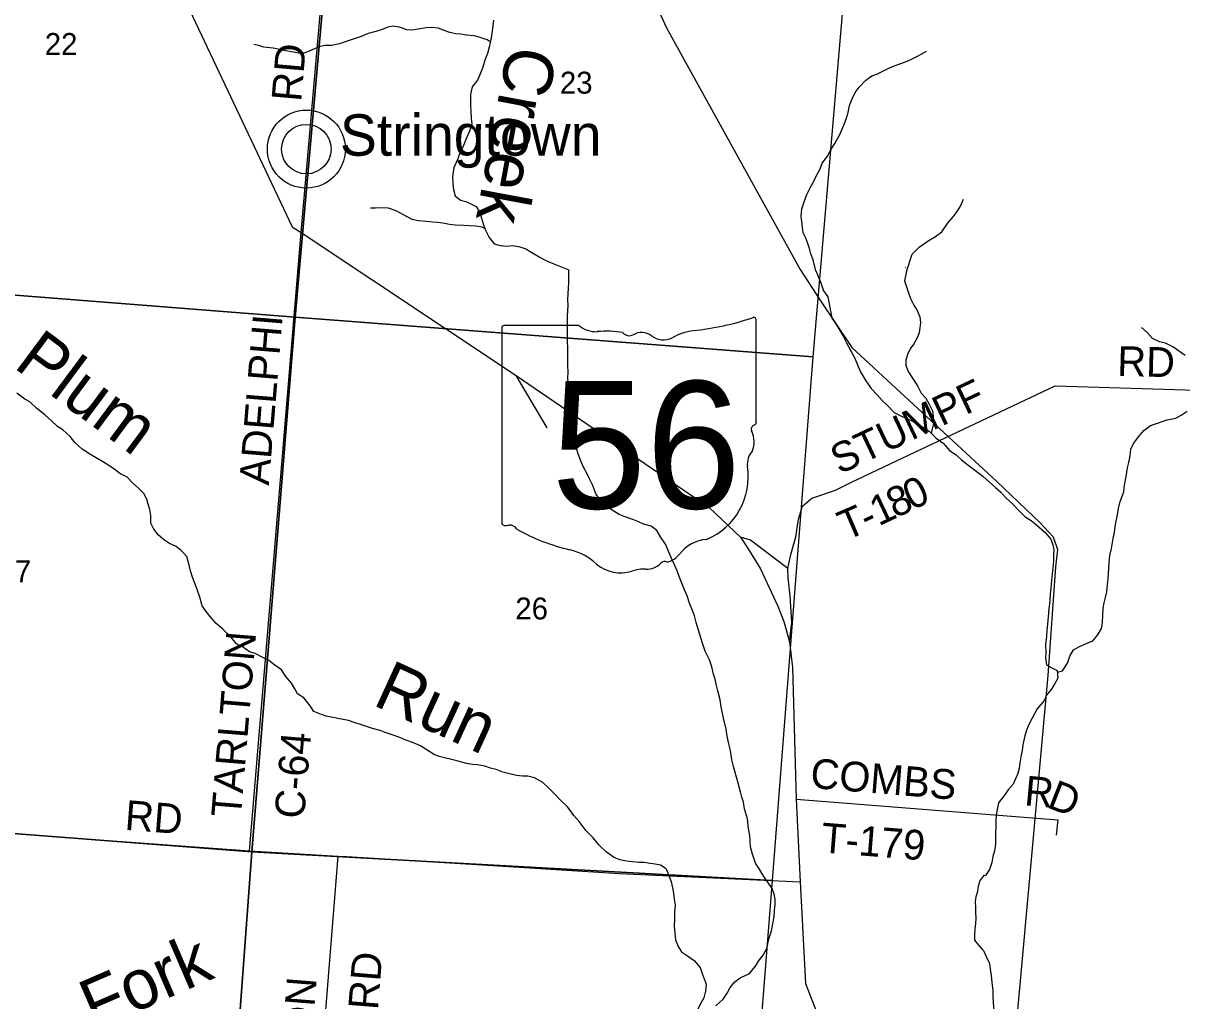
# Model space of a CAD drawing. Extents: x 0 to 42.5, y 0 to 22.
# Drawn here: x 7.006 to 8.111, y 16.014 to 16.947 of the extents above; entities that cross this region are included whole.
import ezdxf

# ---------------------------------------------------------------- set-up
doc = ezdxf.new("R2010")
doc.units = 0
for name, color, linetype in [('GM_X_County_Road', 7, 'Continuous'), ('GM_X_County_Road_Text', 7, 'Continuous'), ('GM_X_Major_River', 7, 'Continuous'), ('GM_X_Major_River_Text', 7, 'Continuous'), ('GM_X_Minor_River', 7, 'Continuous'), ('GM_X_Minor_River_Text', 7, 'Continuous'), ('GM_X_Rail_Line', 7, 'Continuous'), ('GM_X_Section', 7, 'Continuous'), ('GM_X_Section_Text', 7, 'Continuous'), ('GM_X_State_Location', 7, 'Continuous'), ('GM_X_State_Route', 7, 'Continuous'), ('GM_X_State_Shield', 7, 'Continuous'), ('GM_X_Township_Road', 7, 'Continuous'), ('GM_X_Township_Road_Text', 7, 'Continuous'), ('GM_X_Unincorporated', 7, 'Continuous'), ('GM_X_Unincorporated_Location', 7, 'Continuous'), ('GM_X_Unincorporated_Text', 7, 'Continuous')]:
    doc.layers.add(name, color=color, linetype=linetype)

msp = doc.modelspace()

# ---------------------------------------------------------------- linework, layer by layer
at = {"layer": 'GM_X_County_Road'}
for p, q in [((7.222, 16.1571), (7.2714, 16.747)), ((7.222, 16.1571), (7.3065, 16.1521)), ((7.2668, 15.653), (7.3065, 16.1521))]:
    msp.add_line(p, q, dxfattribs=at)
for points in [[(7.2714, 16.747), (7.3073, 17.1594), (7.3439, 17.5804)], [(7.7371, 16.3564), (7.7383, 16.3674), (7.7392, 16.3751), (7.7376, 16.4002), (7.7359, 16.4174), (7.7354, 16.4263), (7.7236, 16.4352), (7.6999, 16.4536), (7.6904, 16.4563)], [(5.989, 16.2475), (6.4831, 16.2121), (6.7307, 16.193), (7.222, 16.1571)], [(7.3065, 16.1521), (7.3148, 16.1517), (7.4441, 16.1437), (7.5749, 16.1355), (7.7471, 16.1274)]]:
    msp.add_lwpolyline(points, dxfattribs=at)
at = {"layer": 'GM_X_Major_River'}
for points in [[(7.4549, 16.9496), (7.4539, 16.9416), (7.4526, 16.9327), (7.4506, 16.9238), (7.4489, 16.9177), (7.4466, 16.9113), (7.4447, 16.9047), (7.4423, 16.899), (7.4395, 16.8924), (7.4345, 16.8859), (7.4329, 16.8785), (7.4327, 16.8736), (7.4327, 16.8685), (7.4333, 16.862), (7.4336, 16.8561), (7.4342, 16.8504), (7.4319, 16.8436), (7.4284, 16.8356), (7.4254, 16.8284), (7.4223, 16.822)], [(7.4223, 16.822), (7.4207, 16.8173), (7.4171, 16.8086), (7.4157, 16.8004), (7.4159, 16.7928), (7.4167, 16.7879), (7.4182, 16.7818), (7.4233, 16.7779), (7.4283, 16.7766), (7.4333, 16.7744), (7.4381, 16.7716), (7.4413, 16.7664), (7.4434, 16.7607), (7.4453, 16.7542), (7.4472, 16.7491), (7.4506, 16.7422), (7.4554, 16.7361), (7.4611, 16.7344), (7.4674, 16.7339), (7.4726, 16.7345), (7.4789, 16.7337), (7.4856, 16.7313), (7.4928, 16.7269), (7.4984, 16.7236), (7.5041, 16.7205), (7.5091, 16.7182), (7.5267, 16.7113)], [(7.6445, 16.3863), (7.6418, 16.3935), (7.6396, 16.4002), (7.6369, 16.4061), (7.6343, 16.4125), (7.632, 16.4188), (7.6298, 16.4241), (7.6273, 16.4298), (7.6241, 16.4369), (7.6215, 16.4437), (7.6188, 16.4496), (7.6141, 16.4567), (7.6105, 16.4628), (7.605, 16.4668), (7.5978, 16.4687), (7.5925, 16.4712), (7.5878, 16.4731), (7.5794, 16.476), (7.5747, 16.4779), (7.5679, 16.4821), (7.5618, 16.4862), (7.5571, 16.4913), (7.5524, 16.4978), (7.5494, 16.5056), (7.5462, 16.5119), (7.5441, 16.5166), (7.5405, 16.5231), (7.5384, 16.5282), (7.5358, 16.5349), (7.5339, 16.5408), (7.5324, 16.5474), (7.5311, 16.5541), (7.5309, 16.5598), (7.5302, 16.5645), (7.5288, 16.5712), (7.5273, 16.5788), (7.5266, 16.586), (7.5262, 16.592), (7.5263, 16.6012), (7.5257, 16.6076), (7.5259, 16.6141), (7.5257, 16.6198), (7.5256, 16.6253), (7.5258, 16.6306), (7.5256, 16.6366), (7.5252, 16.6435), (7.5253, 16.6617), (7.5253, 16.667), (7.5259, 16.6776), (7.5257, 16.6826), (7.5259, 16.6885), (7.5263, 16.6938), (7.5265, 16.6987), (7.5267, 16.7113)], [(7.6669, 16.0092), (7.6739, 16.0157), (7.6777, 16.0213), (7.6806, 16.0266), (7.6848, 16.0321), (7.6901, 16.0359), (7.6988, 16.0402), (7.7045, 16.047), (7.7076, 16.0519), (7.712, 16.0576), (7.7158, 16.0646), (7.7167, 16.0703), (7.7183, 16.076), (7.7198, 16.0809), (7.7209, 16.0857), (7.7225, 16.0942), (7.7227, 16.1003), (7.7233, 16.106), (7.7233, 16.1111), (7.7223, 16.1158), (7.7206, 16.1213), (7.7163, 16.1271), (7.7127, 16.1326), (7.7078, 16.1406), (7.7046, 16.1453), (7.7019, 16.1539), (7.6999, 16.1609), (7.6995, 16.1659), (7.6991, 16.1716), (7.698, 16.1784), (7.6971, 16.1875), (7.6943, 16.197), (7.6933, 16.2035), (7.6916, 16.2084), (7.6903, 16.2134), (7.6892, 16.2181), (7.6879, 16.2229), (7.6838, 16.2375), (7.6822, 16.2438), (7.6808, 16.2527), (7.6791, 16.2593), (7.6776, 16.2666), (7.6768, 16.273), (7.6742, 16.2837), (7.6719, 16.2943), (7.671, 16.3011), (7.6687, 16.3097), (7.6672, 16.316), (7.6661, 16.3207), (7.6646, 16.3256), (7.6631, 16.3327), (7.6609, 16.3393), (7.6567, 16.3475), (7.6541, 16.3551), (7.6526, 16.3602), (7.6503, 16.3677), (7.6482, 16.3749), (7.6464, 16.3812), (7.6445, 16.3863)]]:
    msp.add_lwpolyline(points, dxfattribs=at)
at = {"layer": 'GM_X_Minor_River'}
for points in [[(7.4517, 16.9288), (7.4487, 16.9307), (7.443, 16.9326), (7.4363, 16.9345), (7.429, 16.9352), (7.4237, 16.936), (7.4189, 16.9366), (7.4132, 16.9378), (7.4076, 16.9395), (7.4021, 16.9418), (7.396, 16.9426), (7.3904, 16.9421), (7.3828, 16.941), (7.3776, 16.9399), (7.3721, 16.9403), (7.365, 16.9427), (7.3587, 16.9438), (7.3539, 16.9427), (7.3485, 16.9405), (7.3424, 16.9386), (7.3351, 16.9368), (7.3286, 16.9338), (7.3143, 16.9292), (7.3078, 16.9269), (7.3003, 16.9255), (7.294, 16.9253), (7.289, 16.9244), (7.2789, 16.9199), (7.2739, 16.9181), (7.2689, 16.9181), (7.2639, 16.9191), (7.2567, 16.9201), (7.2494, 16.9218), (7.2446, 16.9228), (7.2358, 16.9238), (7.2311, 16.9254), (7.2263, 16.9262)], [(7.7623, 16.7104), (7.7595, 16.721), (7.7574, 16.7265), (7.756, 16.7316), (7.7545, 16.7364), (7.7528, 16.7415), (7.7501, 16.7467), (7.7494, 16.7518), (7.7488, 16.7573), (7.7483, 16.7621), (7.7489, 16.7695), (7.751, 16.7761), (7.7535, 16.7831), (7.7567, 16.7896), (7.76, 16.7954), (7.7631, 16.8019), (7.7663, 16.8077), (7.7683, 16.813), (7.7733, 16.8198), (7.7767, 16.8266), (7.7802, 16.8319), (7.7852, 16.8406), (7.789, 16.8493), (7.7911, 16.855), (7.7929, 16.8615), (7.7944, 16.8681), (7.7969, 16.8746), (7.7998, 16.8804), (7.8036, 16.8857), (7.8096, 16.8921), (7.8155, 16.8963), (7.8203, 16.8981), (7.8268, 16.9013), (7.8323, 16.9039), (7.8379, 16.9064), (7.8477, 16.9099), (7.8528, 16.9119), (7.8591, 16.9151), (7.8676, 16.9198)], [(7.8488, 16.7099), (7.8541, 16.7264), (7.8607, 16.733), (7.8693, 16.739), (7.8762, 16.7431), (7.8823, 16.7476), (7.8879, 16.7554), (7.8932, 16.762), (7.8969, 16.7671), (7.9001, 16.772), (7.903, 16.7786)], [(7.4465, 16.7508), (7.4441, 16.7519), (7.438, 16.7529), (7.4317, 16.7534), (7.4263, 16.7536), (7.4183, 16.7538), (7.4128, 16.7545), (7.4065, 16.756), (7.4015, 16.7566), (7.3965, 16.7567), (7.3904, 16.7575), (7.3831, 16.7581), (7.3772, 16.7595), (7.369, 16.7639), (7.3621, 16.7676), (7.3547, 16.7701), (7.3489, 16.7705), (7.3422, 16.7702), (7.3374, 16.7702)], [(7.7623, 16.7104), (7.7669, 16.6988), (7.7696, 16.6912), (7.7735, 16.6856), (7.7734, 16.6856)], [(7.8488, 16.7101), (7.8469, 16.7009), (7.8488, 16.6951), (7.8504, 16.6904), (7.8526, 16.684), (7.8558, 16.6777), (7.8589, 16.6724), (7.8615, 16.6665), (7.8619, 16.6612), (7.8615, 16.6559), (7.8609, 16.6511), (7.8584, 16.6458), (7.8556, 16.6409), (7.852, 16.636), (7.8497, 16.6305), (7.8481, 16.6252), (7.8479, 16.6203), (7.85, 16.6151), (7.8532, 16.61), (7.8562, 16.6052), (7.8595, 16.6001), (7.8625, 16.5938), (7.867, 16.5889), (7.8702, 16.5833), (7.8736, 16.5769), (7.8742, 16.5717), (7.8744, 16.5649), (7.8721, 16.5556)], [(7.8474, 16.7139), (7.8476, 16.7134)], [(7.7735, 16.6856), (7.7773, 16.6652), (7.7813, 16.6597), (7.7851, 16.6534), (7.7883, 16.6481), (7.7915, 16.6418), (7.796, 16.6334), (7.7992, 16.6277), (7.8026, 16.6192), (7.8052, 16.6133), (7.81, 16.6056), (7.8149, 16.5982), (7.8206, 16.5921), (7.8253, 16.5868), (7.8304, 16.5818), (7.837, 16.5753), (7.8444, 16.5713), (7.8505, 16.5688), (7.8584, 16.5646), (7.8643, 16.5613), (7.8702, 16.5575), (7.877, 16.5508), (7.8836, 16.5461), (7.8898, 16.539), (7.8961, 16.5348), (7.901, 16.5302), (7.9073, 16.5253), (7.9216, 16.5144)], [(8.1143, 16.6297), (8.1028, 16.6378), (8.0958, 16.6414), (8.0898, 16.6426), (8.0832, 16.6457), (8.0783, 16.6514), (8.0728, 16.6564)], [(7.0869, 16.5253), (7.0812, 16.5287), (7.0753, 16.5324), (7.0697, 16.5354), (7.0626, 16.5402), (7.0556, 16.5467), (7.0511, 16.5522), (7.0439, 16.5587), (7.039, 16.562), (7.0331, 16.5673), (7.0269, 16.5729), (7.0191, 16.5792), (7.0127, 16.5853), (7.0078, 16.5881), (7.0002, 16.5937)], [(7.9925, 16.3275), (7.9973, 16.3289), (8.0022, 16.3361), (8.0044, 16.3427), (8.0078, 16.3489), (8.0135, 16.3519), (8.0209, 16.3553), (8.0263, 16.3574), (8.0312, 16.363), (8.0347, 16.3691), (8.0355, 16.3746), (8.0359, 16.382), (8.0363, 16.3886), (8.0373, 16.3937), (8.0383, 16.3987), (8.0396, 16.4042), (8.0405, 16.4112), (8.0409, 16.4161), (8.0413, 16.4218), (8.0415, 16.4265), (8.0419, 16.432), (8.0427, 16.4389), (8.0441, 16.4455), (8.0457, 16.455), (8.0469, 16.4612), (8.048, 16.4684), (8.05, 16.4777), (8.0508, 16.4838), (8.0524, 16.4902), (8.0558, 16.4997), (8.0566, 16.506), (8.0582, 16.5143), (8.0594, 16.5223), (8.0608, 16.5276), (8.0619, 16.5338), (8.0626, 16.5403), (8.0651, 16.5458), (8.0702, 16.5524), (8.075, 16.558), (8.0813, 16.5627), (8.086, 16.5644), (8.0974, 16.5681), (8.1054, 16.5698), (8.1107, 16.5726), (8.1162, 16.5766)], [(7.6194, 16.1399), (7.6139, 16.1435), (7.609, 16.1443), (7.6043, 16.1449), (7.5986, 16.1459), (7.5933, 16.1461), (7.5874, 16.1467), (7.5817, 16.1473), (7.5753, 16.1486), (7.5692, 16.1511), (7.5622, 16.1561), (7.5554, 16.1624), (7.5499, 16.1694), (7.5431, 16.1761), (7.5365, 16.1851), (7.5314, 16.1908), (7.5257, 16.1988), (7.5183, 16.2058), (7.513, 16.2114), (7.5073, 16.2171), (7.5017, 16.2222), (7.4939, 16.2267), (7.4875, 16.2282), (7.4823, 16.2284), (7.4766, 16.229), (7.47, 16.2306), (7.4636, 16.2321), (7.4573, 16.2346), (7.4518, 16.236), (7.4465, 16.2379), (7.4395, 16.2391), (7.4348, 16.2395), (7.4291, 16.2403), (7.4198, 16.2428), (7.4147, 16.2443), (7.4082, 16.2457), (7.4031, 16.247), (7.3976, 16.2493), (7.3904, 16.2537), (7.3851, 16.2572), (7.3785, 16.2601), (7.3713, 16.2627), (7.3654, 16.2651), (7.3582, 16.2679), (7.3514, 16.2699), (7.3467, 16.272), (7.3395, 16.2739), (7.3345, 16.2753), (7.3288, 16.2774), (7.3228, 16.2793), (7.3165, 16.2814), (7.3063, 16.2832), (7.3002, 16.2847), (7.2951, 16.2857), (7.2881, 16.288), (7.2834, 16.2901), (7.2798, 16.2953), (7.2739, 16.3029), (7.268, 16.3069), (7.2654, 16.3117), (7.262, 16.317), (7.2567, 16.3233), (7.2525, 16.3296), (7.2461, 16.3342), (7.2406, 16.3385), (7.2347, 16.3414), (7.2275, 16.3454), (7.2221, 16.3468), (7.215, 16.352), (7.2096, 16.3546), (7.2039, 16.3615), (7.1967, 16.3686), (7.1899, 16.3743), (7.1846, 16.3806), (7.1808, 16.3855), (7.177, 16.3909), (7.1746, 16.3992), (7.1721, 16.4064), (7.1701, 16.4116), (7.168, 16.4173), (7.1659, 16.4241), (7.1644, 16.4295), (7.1623, 16.438), (7.157, 16.4437), (7.1521, 16.4474), (7.1459, 16.4504), (7.1402, 16.4541), (7.1351, 16.4584), (7.1309, 16.464), (7.1281, 16.4697), (7.1281, 16.4769), (7.127, 16.4828), (7.1255, 16.4877), (7.1242, 16.4925), (7.1213, 16.498), (7.1162, 16.5029), (7.1107, 16.5079), (7.1051, 16.5138), (7.0994, 16.5165), (7.0939, 16.5207), (7.0869, 16.5253)], [(7.9216, 16.5144), (7.9337, 16.5037), (7.9387, 16.4991), (7.9433, 16.4938), (7.9497, 16.4882), (7.9559, 16.4819), (7.9617, 16.4758), (7.9675, 16.4722), (7.973, 16.4678), (7.9809, 16.4609), (7.9862, 16.4544), (7.9882, 16.4491), (7.9891, 16.4441), (7.9889, 16.4394), (7.9887, 16.4343), (7.9885, 16.4295), (7.9877, 16.4214), (7.9869, 16.4151), (7.9862, 16.4073), (7.9858, 16.402), (7.9854, 16.3958), (7.9844, 16.3876), (7.9838, 16.3802), (7.9832, 16.3734), (7.9826, 16.3677), (7.9821, 16.362), (7.9813, 16.3537), (7.9815, 16.3466), (7.9812, 16.3409), (7.9823, 16.3345), (7.9874, 16.3316), (7.9923, 16.3291), (7.993, 16.3219), (7.9898, 16.316), (7.9867, 16.3109), (7.9823, 16.3056), (7.9802, 16.3007), (7.9733, 16.2926), (7.9685, 16.2837), (7.9649, 16.2771), (7.9628, 16.2714), (7.9616, 16.2667), (7.9596, 16.2582), (7.959, 16.2528), (7.9577, 16.2468), (7.9569, 16.2409), (7.9561, 16.2356), (7.9549, 16.2309), (7.9503, 16.2208), (7.9457, 16.2153), (7.9421, 16.2102), (7.9365, 16.2029), (7.9354, 16.1981), (7.9344, 16.1932), (7.9338, 16.1873), (7.9339, 16.1805), (7.9337, 16.1746), (7.9336, 16.1684), (7.9334, 16.1634), (7.9326, 16.1572), (7.9309, 16.1517), (7.9299, 16.1458), (7.9277, 16.1392), (7.9241, 16.1335)], [(7.6194, 16.1399), (7.6243, 16.1277), (7.626, 16.1186), (7.6271, 16.1114), (7.6279, 16.1051), (7.6275, 16.0985), (7.6273, 16.092), (7.6271, 16.0852), (7.6276, 16.0787), (7.6284, 16.0721), (7.6308, 16.0658), (7.6342, 16.0606), (7.6399, 16.0568), (7.646, 16.0524), (7.6518, 16.0458), (7.6539, 16.0402), (7.6558, 16.0351), (7.6575, 16.03), (7.6571, 16.0231), (7.6554, 16.0167), (7.6512, 16.0095), (7.6474, 16.0009)], [(7.9221, 16.062), (7.9181, 16.0669), (7.9138, 16.0719), (7.9138, 16.0774), (7.9142, 16.0824), (7.9149, 16.0879), (7.9152, 16.0929), (7.9149, 16.0983), (7.9149, 16.1034), (7.9145, 16.1085), (7.9152, 16.1135), (7.9167, 16.1186), (7.9174, 16.1236), (7.9189, 16.1287), (7.9232, 16.1338), (7.9241, 16.1335), (7.9239, 16.1338)], [(7.9221, 16.062), (7.9245, 16.0563), (7.9277, 16.0496), (7.9286, 16.0443), (7.9295, 16.0382), (7.9302, 16.0315), (7.9311, 16.0239), (7.9311, 16.0188), (7.9312, 16.0122), (7.9321, 16.005), (7.9338, 15.9983), (7.9358, 15.9932), (7.9381, 15.9884), (7.9401, 15.9829), (7.9405, 15.9753), (7.9395, 15.9706), (7.9358, 15.963), (7.9308, 15.9554), (7.9282, 15.9496), (7.9264, 15.9428), (7.9267, 15.9357), (7.9289, 15.9276)]]:
    msp.add_lwpolyline(points, dxfattribs=at)
at = {"layer": 'GM_X_Rail_Line'}
msp.add_lwpolyline([(7.1679, 18.6952), (7.1875, 18.5321), (7.1959, 18.4941), (7.389, 18.0627), (7.4137, 18.0008), (7.4321, 17.9111), (7.472, 17.6562), (7.5646, 17.1448), (7.5834, 17.0491), (7.6055, 16.9737), (7.6197, 16.9422), (7.7472, 16.7117), (7.7666, 16.6817), (7.7964, 16.6374), (7.9349, 16.5093), (7.976, 16.4699), (7.9885, 16.4565), (7.9926, 16.4444), (7.9907, 16.4281), (7.9835, 16.3244), (7.9483, 15.9349)], dxfattribs=at)
at = {"layer": 'GM_X_Section'}
for points in [[(7.3096, 17.1621), (7.2655, 16.6662), (6.7762, 16.7046), (6.8214, 17.2026)], [(7.8019, 17.1268), (7.7594, 16.6283), (7.2655, 16.6662), (7.3096, 17.1621)], [(6.7762, 16.7046), (7.2655, 16.6662), (7.2242, 16.1562), (6.7311, 16.1941)], [(7.2655, 16.6662), (7.7594, 16.6283), (7.7207, 16.1288), (7.2242, 16.1562)], [(6.7311, 16.1941), (7.2242, 16.1562), (7.1878, 15.6618), (7.1793, 15.6623), (6.6857, 15.6968)], [(7.2242, 16.1562), (7.7207, 16.1288), (7.6812, 15.628), (7.6698, 15.6288), (7.1878, 15.6618)]]:
    msp.add_lwpolyline(points, close=True, dxfattribs=at)
at = {"layer": 'GM_X_State_Route'}
msp.add_lwpolyline([(6.3156, 17.2432), (6.8183, 17.2), (7.0079, 17.1847), (7.0667, 17.0994), (7.1217, 17.04), (7.1566, 16.9771), (7.2629, 16.7523), (7.2714, 16.747), (7.4763, 16.6106), (7.6605, 16.4847), (7.6904, 16.4563), (7.697, 16.446), (7.7094, 16.426), (7.7258, 16.3906), (7.7316, 16.3759), (7.7371, 16.3564), (7.74, 16.3319), (7.7435, 16.2064), (7.7471, 16.1274), (7.7523, 16.0306), (7.7936, 15.9241)], dxfattribs=at)
at = {"layer": 'GM_X_State_Shield'}
for p, q in [((7.4626, 16.6551), (7.4626, 16.4707)), ((7.5361, 16.6582), (7.465, 16.6582)), ((7.7054, 16.5664), (7.7054, 16.6628)), ((7.7054, 16.5664), (7.7054, 16.5664))]:
    msp.add_line(p, q, dxfattribs=at)
for centre, radius, start, end in [((7.6189, 16.9096), 0.2576, 275.8445, 288.9065), ((7.7027, 16.6632), 0.0027, 351.8621, 97.738), ((7.4654, 16.6555), 0.00281, 98.1301, 188.1301), ((7.553, 16.6796), 0.0273, 231.6195, 271.1119), ((7.6518, 16.6019), 0.0518, 97.3462, 120.7689), ((7.5621, 16.5548), 0.098, 80.4867, 94.9883), ((7.5843, 16.6564), 0.00787, 219.7921, 297.1024), ((7.5959, 16.6351), 0.0164, 54.4667, 119.1411), ((7.617, 16.6643), 0.0197, 233.8562, 294.8282), ((7.7026, 16.566), 0.00289, 289.6038, 7.7341), ((7.7048, 16.5593), 0.00418, 107.944, 210.337), ((7.6782, 16.5471), 0.0251, 340.033, 23.6496), ((7.7151, 16.526), 0.0183, 136.8065, 186.9296), ((7.6334, 16.5138), 0.0644, 292.3089, 8.9858), ((7.4654, 16.4703), 0.00284, 171.9584, 258.3066), ((7.4658, 16.4892), 0.0217, 267.339, 280.6039), ((7.4702, 16.4601), 0.00781, 29.7484, 93.2717), ((7.5689, 16.6257), 0.186, 240.4129, 257.1985), ((7.6605, 16.419), 0.0353, 94.4031, 142.5768), ((7.5134, 16.3879), 0.0582, 47.1842, 75.836), ((7.6182, 16.4275), 0.00554, 65.7517, 132.6484), ((7.6158, 16.4529), 0.0208, 282.8732, 323.2771), ((7.5763, 16.4592), 0.0369, 230.7004, 286.2918), ((7.5977, 16.3955), 0.0303, 85.6951, 111.2099), ((7.6004, 16.4454), 0.0197, 268.777, 315.5493)]:
    msp.add_arc(centre, radius, start, end, dxfattribs=at)
at = {"layer": 'GM_X_Township_Road'}
msp.add_line((7.5061, 16.5605), (7.4763, 16.6106), dxfattribs=at)
for points in [[(7.8269, 16.5233), (7.9905, 16.6006), (8.1563, 16.5956), (8.2427, 16.5884), (8.2453, 16.5886), (8.2479, 16.5898)], [(7.7354, 16.4263), (7.7383, 16.4397), (7.743, 16.4567), (7.7458, 16.4736), (7.7494, 16.4859), (7.7583, 16.4936), (7.7811, 16.5013), (7.7962, 16.5088), (7.8269, 16.5233)], [(7.7435, 16.2064), (7.9931, 16.1866), (7.9914, 16.172)]]:
    msp.add_lwpolyline(points, dxfattribs=at)
at = {"layer": 'GM_X_Unincorporated'}
for radius in [0.0372, 0.0236]:
    msp.add_circle((7.2763, 16.8265), radius, dxfattribs=at)
at = {"layer": 'GM_X_Unincorporated_Location'}
msp.add_line((7.2763, 16.8265), (7.2763, 16.8265), dxfattribs=at)

# ---------------------------------------------------------------- texts
at = {"layer": 'GM_X_County_Road_Text'}
for s, rotation, p in [('RD', 85.0737, (7.2713, 16.8712)), ('ADELPHI', 85.3168, (7.2405, 16.5053)), ('TARLTON', 85.285, (7.2138, 16.1883)), ('C-64', 85.208, (7.2741, 16.187)), ('RD', 355.5632, (7.1025, 16.1772)), ('ADELPHI RD', 85.4588, (7.3308, 15.8322)), ('TARLTON', 85.4316, (7.2721, 15.8586))]:
    msp.add_text(s, height=0.02841, rotation=rotation, dxfattribs=at).set_placement(p)
at = {"layer": 'GM_X_Major_River_Text'}
msp.add_text('Creek', height=0.04735, rotation=259.4481, dxfattribs=at).set_placement((7.469, 16.9269))
at = {"layer": 'GM_X_Minor_River_Text'}
for s, rotation, p in [('Plum', 323.4482, (6.996, 16.6187)), ('Run', 335.4487, (7.3383, 16.2968)), ('Fork', 23.3764, (7.0738, 15.9859))]:
    msp.add_text(s, height=0.04735, rotation=rotation, dxfattribs=at).set_placement(p)
at = {"layer": 'GM_X_Section_Text'}
for s, p in [('22', (7.0268, 16.9163)), ('23', (7.5181, 16.8794)), ('27', (6.9827, 16.4132)), ('26', (7.4756, 16.3778))]:
    msp.add_text(s, height=0.02093, rotation=0, dxfattribs=at).set_placement(p)
at = {"layer": 'GM_X_State_Location'}
msp.add_text('56', height=0.0000947, rotation=0, dxfattribs=at).set_placement((7.5549, 16.5337))
for s in ['s', 'r']:
    msp.add_text(s, height=0.0000947, dxfattribs=at).set_placement((7.5788, 16.5406))
at = {"layer": 'GM_X_State_Shield'}
msp.add_text('56', height=0.12144, dxfattribs=at).set_placement((7.51, 16.4837))
at = {"layer": 'GM_X_Township_Road_Text'}
for s, height, rotation, p in [('RD', 0.02841, 358.5184, (8.0494, 16.6102)), ('STUMPF', 0.02841, 25.3129, (7.7848, 16.5158)), ('0', 0.0284, 25.4626, (7.8538, 16.4815)), ('8', 0.0284, 25.4417, (7.838, 16.474)), ('T', 0.0284, 23.2034, (7.791, 16.4527)), ('1', 0.0284, 25.3137, (7.8221, 16.4665)), ('-', 0.0284, 25.009, (7.8114, 16.4615)), ('COMBS', 0.02841, 355.2852, (7.7563, 16.2172)), ('R', 0.0284, 354.71, (7.9604, 16.2006)), ('D', 0.0284, 338.6112, (7.9816, 16.1989)), ('T-179', 0.02841, 355.5152, (7.7665, 16.1557))]:
    msp.add_text(s, height=height, rotation=rotation, dxfattribs=at).set_placement(p)
at = {"layer": 'GM_X_Unincorporated_Text'}
msp.add_text('Stringtown', height=0.03949, rotation=0, dxfattribs=at).set_placement((7.3083, 16.8202))

doc.saveas('drawing.dxf')
